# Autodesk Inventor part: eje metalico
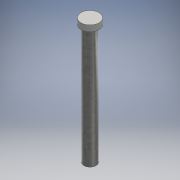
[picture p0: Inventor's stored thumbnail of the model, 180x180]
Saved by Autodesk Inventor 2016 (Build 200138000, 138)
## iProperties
Created: 2016-06
Part Number: eje metalico
Material: Genérico
Document SubType Name: Modeling
Designer: adm
Density: 1 g/cm^3
Appearance: Valor por defecto
Author: adm
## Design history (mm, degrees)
sketch "Boceto1"
  geometry: C1 r 5 at (0, 0); 1 further point
  constraints: 1 centre point, 1 coincident
  dimensions: "d0" = 10 diameter of C1
extrude "Extrusión1" new body sketch "Boceto1" distance "d1" = 100; taper "d2" = 0 deg
sketch "Boceto2"
  geometry: C1 r 7.5 at (0, 0); 1 further point
  constraints: 1 centre point, 1 coincident
  dimensions: "d3" = 15 diameter of C1
extrude "Extrusión2" join sketch "Boceto2" distance "d4" = 5; taper "d5" = 0 deg
node "Sólido1"
